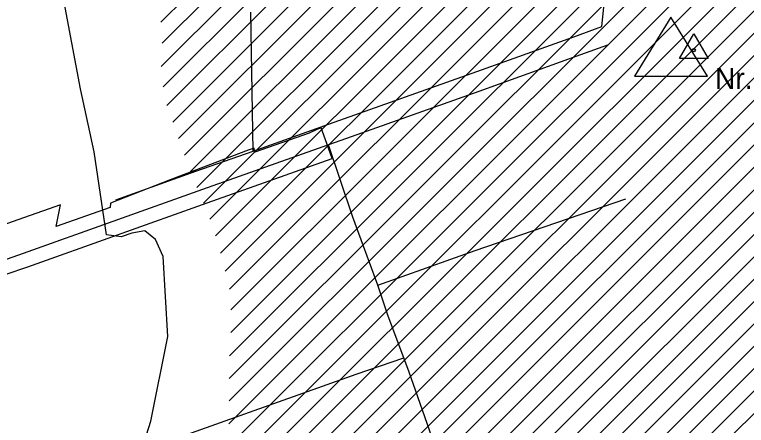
# Model space of a CAD drawing. Extents: x 468834 to 503362, y 294936 to 320859.
# Drawn here: x 478137 to 479062, y 308061 to 308581 of the extents above; entities that cross this region are included whole.
import ezdxf

# ---------------------------------------------------------------- set-up
doc = ezdxf.new("R2010")
doc.units = 0
for name, color, linetype in [('1020101_TIN11_plūdu riska teritorija', 7, 'Continuous'), ('7312030303_ekspluatācijas aizsargjoslas teritorija gar valsts vietējiem un pašvaldību autoceļiem lauku apvidos', 7, 'Continuous'), ('aizkrāsojums-poldera teritorija', 7, 'Continuous'), ('Koplietošanas novadgrāvis', 7, 'Continuous'), ('Potenciāli piesārņota vieta', 7, 'Continuous'), ('Teksts', 7, 'Continuous'), ('Vietējā ģeodēziskā tīkla punkti', 7, 'Continuous')]:
    doc.layers.add(name, color=color, linetype=linetype)

msp = doc.modelspace()

# ---------------------------------------------------------------- linework, layer by layer
at = {"layer": '1020101_TIN11_plūdu riska teritorija'}
msp.add_lwpolyline([(478281.37, 307978.91), (478309.19, 308066.93), (478330.42, 308173.66), (478324.62, 308274.92), (478315.15, 308296.45), (478301.62, 308307.33), (478285.21, 308304.43), (478271.51, 308300.07), (478253.02, 308302.35), (478237.35, 308407.25), (478220.03, 308487.11), (478198.08, 308603.78)], dxfattribs=at)
at = {"layer": '7312030303_ekspluatācijas aizsargjoslas teritorija gar valsts vietējiem un pašvaldību autoceļiem lauku apvidos'}
for p, q in [((478518.72, 308435.82), (478509.12, 308430.92)), ((478524.52, 308437.8), (478518.72, 308435.82)), ((478531.63, 308417.8), (478524.52, 308437.8)), ((478509.12, 308430.92), (478440.49, 308406.92)), ((478538.28, 308399.08), (478531.63, 308417.8)), ((478432.25, 308409.42), (478333.59, 308372.03)), ((478439.52, 308412.18), (478432.25, 308409.42)), ((478440.49, 308406.92), (478439.52, 308412.18)), ((478333.59, 308372.03), (478257.99, 308342.32)), ((478189.48, 308312.92), (478194.95, 308340.6)), ((478257.99, 308342.32), (478257.9, 308337.04)), ((478257.9, 308337.04), (478189.48, 308312.92))]:
    msp.add_line(p, q, dxfattribs=at)
for points in [[(478016.66, 308215.57), (478019.06, 308215.76), (478029.57, 308217.84), (478038.85, 308220.75), (478069.34, 308232.17), (478098.79, 308243.05), (478126.12, 308252.5), (478153.8, 308262.18), (478267.11, 308302.66), (478380.31, 308343.08), (478538.28, 308399.08)], [(478194.95, 308340.6), (478133.81, 308318.75), (478106.41, 308309.17), (478078.59, 308299.54), (478048.42, 308288.41), (478012.85, 308275.09)]]:
    msp.add_lwpolyline(points, dxfattribs=at)
at = {"layer": 'aizkrāsojums-poldera teritorija'}
for p, q in [((478336.83, 308445.17), (479232.1, 309340.44)), ((478344.24, 308424.29), (479262.16, 309342.21)), ((478351.64, 308403.41), (479289.18, 309340.94)), ((477570.65, 306887.02), (480014.69, 309331.07)), ((478329.43, 308466.05), (479195.78, 309332.4)), ((478359.14, 308382.62), (479314.69, 309338.17)), ((478367.34, 308362.54), (479339.41, 309334.61)), ((478408.33, 308233.83), (479506.02, 309331.51)), ((478410.22, 308207.43), (479532.09, 309329.3)), ((477557.08, 307014.88), (479862.49, 309320.29)), ((477559.8, 306989.31), (479892.06, 309321.57)), ((477562.51, 306963.74), (479922.25, 309323.48)), ((477565.22, 306938.17), (479953.14, 309326.08)), ((477567.94, 306912.59), (479983.98, 309328.64)), ((478375.55, 308342.46), (479359.38, 309326.29)), ((478402.83, 308256.61), (479470.51, 309324.29)), ((478408.26, 308120.61), (479610.31, 309322.67)), ((478408.26, 308092.33), (479636.39, 309320.46)), ((478408.57, 308149.21), (479584.24, 309324.88)), ((478409.99, 308178.91), (479558.17, 309327.09)), ((477546.23, 307117.16), (479744.92, 309315.86)), ((477548.94, 307091.59), (479773.89, 309316.54)), ((477551.66, 307066.02), (479803.37, 309317.73)), ((477554.37, 307040.45), (479832.93, 309319.01)), ((477573.36, 306861.45), (480029.08, 309317.17)), ((478383.75, 308322.38), (479380.85, 309319.48)), ((478390.83, 308301.18), (479406.85, 309317.2)), ((478391.83, 307991.05), (479715.75, 309314.97)), ((478397.12, 308279.18), (479436.13, 309318.19)), ((478404.99, 308032.49), (479689.17, 309316.67)), ((478407.58, 308063.37), (479662.59, 309318.38)), ((478321.83, 308571.59), (479014.56, 309264.31)), ((477576.4, 306836.2), (479990.94, 309250.75)), ((478323.49, 308544.96), (479026.01, 309247.48)), ((478322.04, 308515.23), (479037.83, 309231.01)), ((478324.63, 308489.53), (479059.05, 309223.95)), ((477579.55, 306811.07), (479975.76, 309207.28)), ((477582.7, 306785.94), (479979.02, 309182.26)), ((477585.86, 306760.81), (479988.17, 309163.12)), ((477589.01, 306735.68), (480000.26, 309146.93)), ((477592.16, 306710.55), (480012.51, 309130.89)), ((477595.32, 306685.42), (480021.44, 309111.54)), ((477598.47, 306660.29), (480030.14, 309091.96)), ((477601.62, 306635.16), (480038.22, 309071.75)), ((477604.78, 306610.02), (480039.42, 309044.67))]:
    msp.add_line(p, q, dxfattribs=at)
at = {"layer": 'Koplietošanas novadgrāvis'}
for points in [[(478879.23, 308565.9), (478900.38, 308774.61)], [(478438.22, 308408.43), (478435.33, 308584.08)], [(478438.22, 308408.43), (478540.82, 308444.81), (478715.39, 308506.88), (478843.62, 308553), (478879.23, 308565.9)], [(478886.16, 308542.36), (478851.94, 308529.96), (478851.92, 308529.95), (478723.66, 308483.82), (478723.64, 308483.82), (478723.63, 308483.81), (478549.01, 308421.72), (478533.47, 308416.21)], [(478533.47, 308416.21), (478374.36, 308359.8), (478261.14, 308319.38), (478147.92, 308278.93), (478147.89, 308278.92), (478147.85, 308278.9), (478120.3, 308269.27), (478120.29, 308269.27), (478120.27, 308269.26), (478092.81, 308259.76), (478063.15, 308248.81), (478033.33, 308237.64), (478033.07, 308237.55), (478032.81, 308237.46), (478025.71, 308235.23), (478025.17, 308235.08), (478024.63, 308234.95), (478021.98, 308234.43)], [(478595.9, 308238.88), (478564.19, 308324.87), (478533.47, 308416.21)], [(478264.65, 308346.65), (478366.14, 308382.88), (478366.16, 308382.89), (478438.22, 308408.43)], [(478718.98, 308282.82), (478909.49, 308348.11)], [(478595.9, 308238.88), (478718.98, 308282.82)], [(478628.68, 308146.85), (478609.05, 308199.57), (478596.37, 308237.6), (478595.9, 308238.88)], [(478568.77, 308126.06), (478628.68, 308146.85)], [(478640.92, 308113.03), (478635.38, 308128.87), (478628.68, 308146.85)], [(478078.74, 307951.45), (478568.77, 308126.06)], [(478694.13, 307963.47), (478678.77, 308004.91), (478640.92, 308113.03)]]:
    msp.add_lwpolyline(points, dxfattribs=at)
at = {"layer": 'Potenciāli piesārņota vieta'}
for p, q in [((478966.44, 308577.97), (478920.19, 308503.24)), ((479012.68, 308503.24), (478966.44, 308577.97)), ((478920.19, 308503.24), (479012.68, 308503.24))]:
    msp.add_line(p, q, dxfattribs=at)
at = {"layer": 'Vietējā ģeodēziskā tīkla punkti'}
for p, q in [((478977.28, 308525.62), (478995.28, 308556.79)), ((478995.28, 308556.79), (479013.28, 308525.62)), ((479013.28, 308525.62), (478977.28, 308525.62))]:
    msp.add_line(p, q, dxfattribs=at)
msp.add_circle((478995.28, 308536.01), 2, dxfattribs=at)

# ---------------------------------------------------------------- texts
at = {"layer": 'Teksts'}
msp.add_text('Nr.2', height=26.542, dxfattribs=at).set_placement((479022.24, 308487.03))

doc.saveas('drawing.dxf')
